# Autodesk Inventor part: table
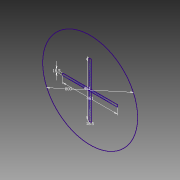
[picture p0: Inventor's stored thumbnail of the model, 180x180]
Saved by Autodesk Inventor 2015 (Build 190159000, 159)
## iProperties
Created: 2017-06
Part Number: table
Material: Generic
Document SubType Name: Modeling
Designer: mcalderon
Density: 1 g/cm^3
Appearance: Default
Author: mcalderon
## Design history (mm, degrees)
sketch "Sketch1"
  geometry: L1 (-230.5, 9.25)-(230.5, 9.25); L2 (230.5, 9.25)-(230.5, -9.25); L3 (230.5, -9.25)-(-230.5, -9.25); L4 (-230.5, -9.25)-(-230.5, 9.25); L5 (-230.5, 9.25)-(230.5, -9.25); L6 (230.5, 9.25)-(-230.5, -9.25); L7 (-9.25, 230.5)-(9.25, 230.5); L8 (9.25, 230.5)-(9.25, -230.5); L9 (9.25, -230.5)-(-9.25, -230.5); L10 (-9.25, -230.5)-(-9.25, 230.5); L11 (-9.25, 230.5)-(9.25, -230.5); L12 (9.25, 230.5)-(-9.25, -230.5); C1 r 400 at (0, 0); 1 further point
  constraints: 24 end point, 4 midpoint, 4 parallel, 2 horizontal, 2 perpendicular, 1 centre point, 1 coincident
  dimensions: "d0" = 800 diameter of C1; "d1" = 461 distance of L2.end L3.end; "d2" = 18.5 distance of L1.end L2.end; "d3" = 18.5 distance of L8.end L9.end; "d4" = 461 distance of L7.end L8.end
